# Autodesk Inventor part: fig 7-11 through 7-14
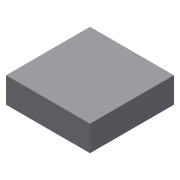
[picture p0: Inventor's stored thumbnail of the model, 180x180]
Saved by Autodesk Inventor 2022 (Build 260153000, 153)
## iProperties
Created: 2009-09
Part Number: fig 7-11 through 7-14
Document SubType Name: Modeling
Designer: Sham
Density: 1 g/cm^3
Material: Generic
Appearance: Default
Author: Sham
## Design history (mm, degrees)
sketch "Sketch1"
  geometry: L1 (-23, 20)-(0, 20); L2 (0, 20)-(0, -3); L3 (0, -3)-(-23, -3); L4 (-23, -3)-(-23, 20)
  constraints: 8 end point, 2 parallel, 1 horizontal, 1 perpendicular
  dimensions: "d2" = 23 distance of L1.start L1.end; "d3" = 23 distance of L3.end L1.start
extrude "Extrusion1" new body sketch "Sketch1" distance "d0" = 7; taper "d1" = 0 deg
body "Solid1"
